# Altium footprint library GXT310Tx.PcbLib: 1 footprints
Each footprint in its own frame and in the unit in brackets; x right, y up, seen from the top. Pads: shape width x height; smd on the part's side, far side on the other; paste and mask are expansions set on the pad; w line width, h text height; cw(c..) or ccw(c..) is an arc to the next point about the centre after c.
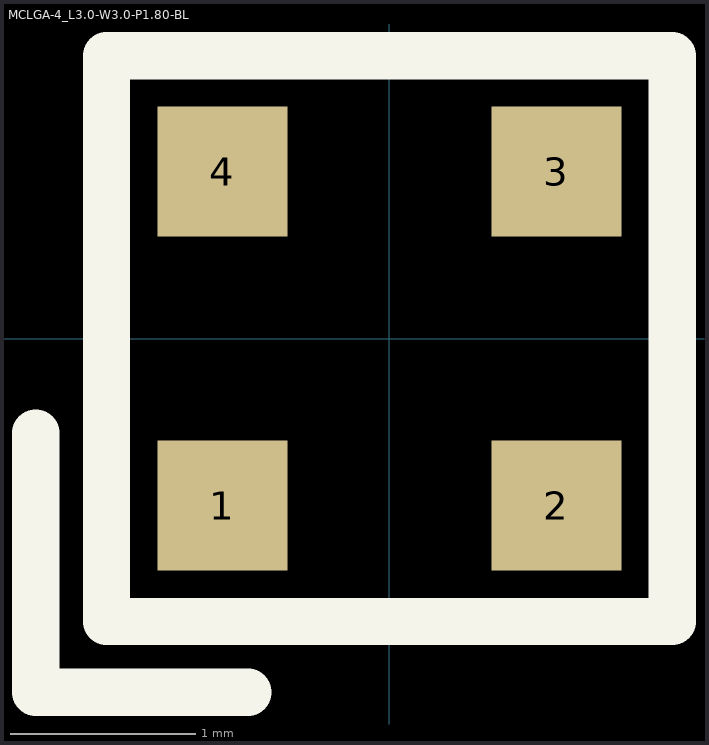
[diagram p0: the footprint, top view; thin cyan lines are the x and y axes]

## MCLGA-4_L3.0-W3.0-P1.80-BL [mm]
pads (4):
  rect 0.7x0.7 smd: 1(-0.9,-0.9) 2(0.9,-0.9) 3(0.9,0.9) 4(-0.9,0.9)
Top Overlay:
  lines w0.254: -1.905,-0.508 -1.905,-1.905 -0.762,-1.905 ; -1.524,-1.524 1.524,-1.524 1.524,1.524 -1.524,1.524 -1.524,-1.524
3D body "MCLGA-4-3.00X3.00-P1.8.STEP": height 1.01, standoff 0, extent -1.527,-1.5 1.473,1.5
